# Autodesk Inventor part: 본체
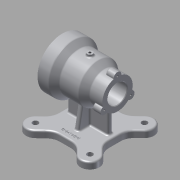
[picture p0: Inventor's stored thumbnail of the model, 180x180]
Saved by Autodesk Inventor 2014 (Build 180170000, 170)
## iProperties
Created: 2017-03
Part Number: 본체
Material: 알루미늄 6061
Document SubType Name: Modeling
Designer: SCD-A13
Density: 2.71 g/cm^3
Appearance: 알루미늄 - 평지
Mass: 1010.08 g
Surface Area: 843.409 cm^2
Volume: 372.724 cm^3
Author: SCD-A13
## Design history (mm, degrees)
sketch "스케치1"
  geometry: L1 (50, 45)-(50, 18.5); L2 (50, 0)-(-50, 0); L3 (-50, 36)-(-50, 45); L4 (-50, 45)-(-31.071, 45); L5 (-17.929, 36)-(14.045, 36); L6 (-19.829, 36.678)-(-29.171, 44.322); L7 (27.955, 27.5)-(50, 27.5); L8 (15.779, 35.448)-(26.221, 28.052); L9 (49, 17.5)-(23, 17.5); L10 (17, 26)-(-24, 26); L11 (-30, 35)-(-49, 35); L12 (-27, 32)-(-27, 29); L13 (20, 20.5)-(20, 23); L14 (-49, 35)-(-50, 36); L15 (49, 17.5)-(50, 18.5); A1 r 3 centre (-17.929, 39) between (-19.829, 36.678) and (-17.929, 36); A2 r 3 centre (-31.071, 42) between (-29.171, 44.322) and (-31.071, 45); A3 r 3 centre (14.045, 33) between (15.779, 35.448) and (14.045, 36); A4 r 3 centre (27.955, 30.5) between (26.221, 28.052) and (27.955, 27.5); A5 r 3 centre (-30, 32) between (-27, 32) and (-30, 35); A6 r 3 centre (-24, 29) between (-27, 29) and (-24, 26); A7 r 3 centre (17, 23) between (20, 23) and (17, 26); A8 r 3 centre (23, 20.5) between (20, 20.5) and (23, 17.5); 13 further points
  constraints: 30 end point, 27 point on line, 16 point on circle, 16 tangent, 8 centre point, 5 equal radius, 5 parallel, 3 perpendicular
  dimensions: "d0" = 100 distance of L3.end L1.start; "d2" = 0 vertical distance of point (0, 0) L2.start; "d4" = 50 horizontal distance of L3.end point (0, 0); "d10" = 90 diameter of L4 L2; "d12" = 72 diameter of L5 L2; "d13" = 20 distance of L3.end point (-30, 45); "d15" = 31 horizontal distance of point (-19, 36) L3.end; "d18" = 55 diameter of L7 L2; "d19" = 23 distance of point (27, 27.5) L7.end; "d20" = 65 horizontal distance of L3.end point (15, 36); "d21" = 3 radius of A1; "d22" = 30 distance of point (50, 17.5) point (20, 17.5); "d23" = 35 diameter of L9 L2; "d24" = 47 distance of point (20, 26) point (-27, 26); "d25" = 52 diameter of L10 L2; "d26" = 23 distance of point (-27, 35) point (-50, 35); "d27" = 70 diameter of L11 L2; "d28" = 3 radius of A5; "d29" = 3 radius of A7; "d30" = 1 distance of L11.end point (-50, 35); "d31" = 1 distance of L3.start point (-50, 35) (= d30); "d32" = 1 distance of L9.start point (50, 17.5) (= d30); "d33" = 1 distance of L1.end point (50, 17.5) (= d32)
revolve "회전1" sketch "스케치1" stored, may be unused: angle "d34" = 90 deg
sketch "스케치2"
  geometry: C1 r 7 at (0, 27.5); 2 further points
  constraints: 1 centre point, 1 coincident, 1 vertical alignment, 1 other
  dimensions: "d35" = 14 diameter of C1
extrude "돌출1" join sketch "스케치2" distance "d36" = 15; taper "d37" = 0 deg
hole "구멍1" sketch "스케치2" diameter "d38" = 3.242; stored, may be unused: countersink angle "d42" = 90 deg, drill point angle "d44" = 118 deg; dims "d39" = 9, "d40" = 4, "d41" = 2, "d43" = 11
fillet "모깎기1" dims "d45" = 3, "d46" = 1
sketch "스케치3" dims "d50" = 80
  geometry: C1 r 45 at (0, 0) reference; 2 further points
  constraints: 1 coincident, 1 vertical alignment, 2 other
hole "구멍2" sketch "스케치3" at (0, -40) diameter "d51" = 3.242; stored, may be unused: countersink angle "d55" = 90 deg, drill point angle "d57" = 118 deg; dims "d52" = 9, "d53" = 4, "d54" = 2, "d56" = 11
node "작업 평면1"
sketch "스케치4"
  geometry: L1 (60.496, -37.271)-(51.622, -28.404); L2 (36.462, -61.321)-(28.261, -53.125); L3 (-37.67, 61.708)-(-28.478, 52.516); L4 (-61.712, 37.666)-(-52.701, 28.656); L5 (60.639, 37.232)-(52.224, 29.415); L6 (37.499, 62.142)-(28.488, 53.772); L7 (-44.996, 10.607)-(-44.995, 6.817); L8 (45.001, -12.42)-(45.006, 11.855); L9 (9.62, 45.188)-(-10.803, 45.192); L10 (10.595, -45.809)-(-11.429, -45.804); L11 (-44.999, -10.589)-(-44.995, 6.817); L12 (37, -4)-(-37, -4); L13 (-37, -4)-(-37, 4); L14 (-37, 4)-(37, 4); L15 (37, 4)-(37, -4); L16 (4, -25)-(-4, -25); L17 (-4, -25)-(-4, 25); L18 (-4, 25)-(4, 25); L19 (4, 25)-(4, -25); L20 (-52.699, -28.63)-(-61.455, -37.024); L21 (-28.735, -52.757)-(-37.926, -61.568); C1 r 5 at (48.479, -49.296); C2 r 5 at (-49.691, 49.687); C3 r 5 at (-49.691, -49.296); C4 r 5 at (49.069, 49.687); A1 r 17 centre (48.479, -49.296) between (36.462, -61.321) and (60.496, -37.271); A2 r 22.59 centre (67.59, -12.425) between (45.001, -12.42) and (51.622, -28.404); A3 r 25 centre (10.589, -70.809) between (28.261, -53.125) and (10.595, -45.809); A4 r 17 centre (-49.691, 49.687) between (-37.67, 61.708) and (-61.712, 37.666); A5 r 25.004 centre (-10.798, 70.196) between (-28.478, 52.516) and (-10.803, 45.192); A6 r 25.001 centre (-69.997, 10.603) between (-44.996, 10.607) and (-52.701, 28.656); A7 r 17 centre (-49.691, -49.296) between (-61.455, -37.024) and (-37.926, -61.568); A8 r 25 centre (-11.434, -70.804) between (-11.429, -45.804) and (-28.735, -52.757); A9 r 25 centre (-69.999, -10.583) between (-52.699, -28.63) and (-44.999, -10.589); A10 r 24.984 centre (69.99, 11.849) between (52.224, 29.415) and (45.006, 11.855); A11 r 17 centre (49.069, 49.687) between (60.639, 37.232) and (37.499, 62.142); A12 r 25.014 centre (9.626, 70.202) between (9.62, 45.188) and (28.488, 53.772); 1 further point
  constraints: 42 end point, 24 point on circle, 16 centre point, 15 tangent, 7 parallel, 4 coincident, 4 perpendicular, 2 horizontal, 2 other
  dimensions: "d72" = 74 distance of L13.end L14.end; "d73" = 8 distance of L12.end L13.end; "d74" = 8 distance of L17.end L18.end; "d75" = 50 distance of L16.end L17.end; "d76" = 4 horizontal distance of L16.start point (0, 0); "d77" = 4 vertical distance of L12.end point (0, 0); "d78" = 37 horizontal distance of L12.start point (0, 0); "d79" = 25 vertical distance of L16.end point (0, 0); "d108" = 34 distance between parallel lines of L20 L21; "d109" = 90 distance between parallel lines of L8 L11; "d110" = 34 distance between parallel lines of L1 L2; "d111" = 34 distance between parallel lines of L6 L5; "d112" = 34 distance between parallel lines of L4 L3; "d117" = 17 radius of A1; "d118" = 17 radius of A4; "d119" = 17 radius of A11; "d120" = 0 vertical distance of A1.centre A7.centre; "d121" = 0 horizontal distance of A4.centre A7.centre; "d122" = 0 vertical distance of C4.centre A4.centre
extrude "돌출2" join sketch "스케치4" distance "d80" = 12; taper "d81" = 0 deg
extrude "돌출3" join sketch "스케치4" stored distance "d82" = 12; taper "d83" = 0 deg
sketch "스케치5"
  geometry: L1 (-4, -25)-(-4, 25) reference; L2 (4, -25)-(-4, -25) reference; L3 (4, 25)-(4, -25) reference; L4 (-4, 25)-(4, 25) reference; 1 further point
  dimensions: "d106" = 25 vertical distance of L1.start point (0, 0) (derived); "d107" = 25 vertical distance of L1.end point (0, 0) (derived)
extrude "돌출4" join sketch "스케치5" stored distance "d84" = 12; taper "d85" = 0 deg
feature "면 기울기1" dims angle "d86" = 10 deg
feature "면 기울기2" dims angle "d87" = 10 deg
fillet "모깎기2" dims "d88" = 3
node "작업 평면2"
sketch "스케치6"
  geometry: C1 r 5 at (0, 0); 3 further points
  constraints: 3 coincident, 1 centre point
  dimensions: "d90" = 10 diameter of C1
extrude "돌출5" join sketch "스케치6" stored distance "d92" = 12; taper "d93" = 0 deg
hole "구멍3" sketch "스케치6" diameter "d94" = 4.134; stored, may be unused: countersink angle "d98" = 90 deg, drill point angle "d100" = 118 deg; dims "d95" = 15, "d96" = 4, "d97" = 2, "d99" = 15
fillet "모깎기3" dims "d101" = 3
sketch "스케치7"
  geometry: L1 (7, -21.425)-(7, -7) reference; L2 (0, 0)-(0, -35); 5 further points; 1 other entity
  constraints: 2 coincident, 2 end point, 1 parallel, 2 other
  dimensions: "d102" = 35 distance of L2.start L2.end; "d103" = 44.98864 dimension on L2.end (derived)
feature "엠보싱1" sketch "스케치7" dims "d0" = 100, "d2" = 0, "d4" = 50, "d10" = 90, "d12" = 72, "d13" = 20, "d15" = 31, "d18" = 55, "d19" = 23, "d20" = 65, "d21" = 3, "d22" = 30, "d23" = 35, "d24" = 47, "d25" = 52, "d26" = 23, "d27" = 70, "d28" = 3, "d29" = 3, "d30" = 1, "d31" = 1 (= d30), "d32" = 1 (= d30), "d33" = 1 (= d32), "d104" = 0.5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
node "솔리드1"
pattern_circular "원형 패턴1" dims "d48" = 360 deg
pattern_circular "원형 패턴2" dims angle "d59" = 360 deg
other parameters: "d61" = -82
